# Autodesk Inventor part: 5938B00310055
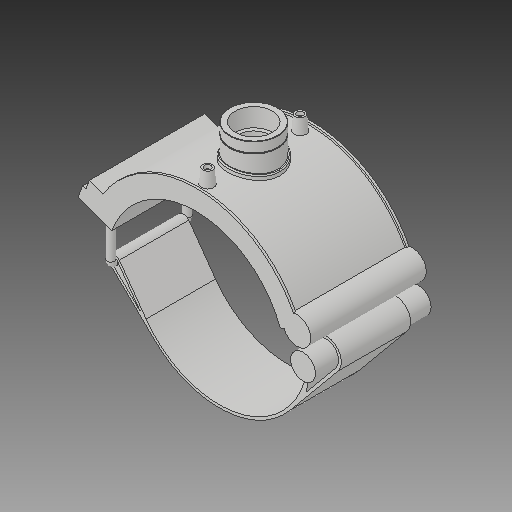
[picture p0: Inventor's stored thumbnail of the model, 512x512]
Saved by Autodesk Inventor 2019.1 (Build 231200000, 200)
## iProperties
Created: 2017-07
Part Number: 5938B00310055
Material: Generic
Description: PLASSON TRANSITION SADDLE 10''IPS x 2"NPT
Document SubType Name: Modeling
Designer: KIM
Density: 1 g/cm^3
Appearance: Default
Author: KIM
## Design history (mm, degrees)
derived "5938B.ipt"
feature "Solid1::5938B.ipt"
tag "TaggingFeature1"
body "Solid1"
other parameters: "d0" = 272.7, "d1" = 327.24, "d2" = 450.85, "d3" = 68.175, "d4" = 176.022, "d5" = 0, "d40" = 170.1648, "d41" = 79.3184, "d43" = 0, "d45" = 0, "d47" = 210.356, "d48" = 73.6528, "d50" = 0, "d78" = 185.62, "d79" = 15, "d80" = 70.4088, "d82" = 5 deg, "d84" = 4, "d85" = 14, "d86" = 0, "d87" = 3, "d88" = 0, "d96" = 333.7848, "d97" = 3.52044, "d98" = 0, "d102" = 1.69968, "d103" = 56.656, "d104" = 28.0416, "d105" = 0, "d106" = 45.3248, "d108" = 0, "d109" = -15.57867, "d111" = 0.5, "d112" = 0.5, "d113" = 0, "d114" = 0.5, "d117" = 0.56656, "d120" = 140 deg, "d121" = 24.228, "d122" = 20 deg, "d123" = 1308.96, "d124" = 196.344, "d126" = 0, "d143" = 280.881, "d145" = 41.95385, "d149" = 4.0905, "d150" = 46.14923, "d153" = 176.022, "d154" = 0, "d156" = 163.62, "d157" = 160 deg, "d159" = 10.908, "d161" = 4.0905, "d162" = 105.6132, "d163" = 0, "d164" = 136.35, "d167" = 27.27, "d168" = 159.62927, "d170" = 4.0905, "d172" = 0, "d173" = 1, "d175" = 136.35, "d176" = 20 deg, "d177" = 19.089, "d178" = 54.54, "d180" = 0, "d183" = 21.816, "d184" = 15.2712, "d185" = 57.20715, "d186" = 57.20715, "d187" = 163.62, "d188" = 16.362, "d189" = 19.089, "d190" = 0, "d191" = 196.344, "d193" = 10.908, "d194" = 5.59035, "d195" = 90 deg, "d197" = 0, "d199" = 0, "d_" = 272.7, "B_" = 180.34, "H_" = 46.736, "L_" = 176.022, "d_t" = 6, "G_" = 56.656, "d148" = 4.0905, "d160" = 4.0905, "d169" = 4.0905, "d192" = 10.908
